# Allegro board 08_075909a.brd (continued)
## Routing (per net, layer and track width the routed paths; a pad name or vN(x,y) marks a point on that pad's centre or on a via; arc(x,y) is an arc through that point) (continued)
THERM: length 154.3
  TOP w0.254: 58.17,112.01 58.79,112.01 59.95,110.85 59.97,110.85 U1.29
  TOP w0.635: J2.13 42.04,115.32 45.47,115.32 48.9,111.89 54.33,111.89 C14.1 55.12,112.01 58.17,112.01
  BOTTOM w0.635: 31.75,165.66 30.78,166.62 23.24,166.62 22.61,165.99 R128.1 22.61,163.6 ; 31.75,165.66 R127.1 ; 31.75,165.66 32.84,166.75 46.99,166.75 48.51,165.23
  BOTTOM w0.762: THERM.1 J5.22 ; J2.13 36.07,121.28
  BOTTOM w0.889: 58.67,165.35 58.67,165.48 57.66,166.5 49.78,166.5 48.51,165.23 R126.1 ; 58.67,165.35 R124.1 ; 58.67,165.35 59.82,166.5 67.82,166.5 68.83,165.48 ; 68.83,165.48 69.98,166.62 77.85,166.62 79.38,165.1 R122.1 ; 68.83,165.48 R123.1 ; 36.07,121.28 THERM.1 ; 22.61,163.6 22.23,163.6 22.17,163.55 22.04,163.55 21.38,162.89 21.38,161.5 21.48,161.4 21.48,161.37 21.85,161 21.87,161 22.17,160.71 24.12,158.75 29.34,158.75 36.07,152.02 J5.21 J5.22
TXLN: length 14.9
  TOP w0.203: R14.1 30.27,142.88 R157.2 27.98,141.59 27.45,141.06 27.45,139.95 D31.C 27.66,139.8 R150.1 TXLN.1
  TOP w0.305: R151.2 25.65,140.21 25.91,139.95 27.45,139.95
TXLN_SDI: length 57.8
  TOP w0.203: 67.61,133.93 67.61,133.65 65.37,131.41 R8.1 R2.2 ; 67.61,133.93 67.87,133.93 69.37,135.43 69.37,137.03 68.99,137.41 70.38,137.41 71.07,138.1 71.07,142.41 69.53,143.94 33.2,143.94 32.26,143 R14.2 ; 67.61,133.93 67.22,134.32 Q1.1
  TOP w0.254: 68.99,137.41 J1.16
TXLNSDI: length 21.3
  TOP w0.203: 69.12,116.97 69.97,116.97 70.76,117.76 70.76,119.29 62.87,127.19 62.87,128.27 63.7,129.11 63.7,130.17 R8.2 ; 69.12,116.97 69.12,116.08 U1.16 ; 69.12,116.97 69.12,116.97 C82.1
TXLP: length 14.7
  TOP w0.203: 27.45,148.59 27.45,147.68 27.98,147.15 R160.2 30.27,145.67 R16.1 ; 27.45,148.59 D28.C 27.66,148.75 R152.1 TXLP.1 ; 27.45,148.59 25.65,148.59 25.4,148.34 R154.2
TXLP_SDO: length 58.7
  TOP w0.203: R16.2 32.13,145.54 33.27,144.4 69.72,144.4 71.53,142.6 71.53,137.91 70.69,137.07 J1.15 70.31,135.71 67.23,132.64 ; 67.23,132.64 65.81,131.22 65.81,130.46 R7.1 67.53,128.74 R4.2 ; 67.23,132.64 67.23,132.51 Q1.4
TXLPSDO: length 21.2
  TOP w0.203: 70.29,115.81 69.55,115.81 68.8,115.05 U1.15 ; 70.29,115.81 C78.1 ; 70.29,115.81 70.21,115.88 70.21,116.63 70.91,117.33 70.91,117.33 71.17,117.58 71.17,119.46 63.27,127.36 63.27,128.09 64.03,128.85 65.02,128.85 R7.2
TXN1: length 14.6
  TOP w0.203: v1(4.17,143.87) 4.32,144.02 6.48,144.02 6.92,143.57 TXLP_CONN.1 7.84,139.48 TXN1.1
  BOTTOM w0.203: R20.1 11.11,138.3 TXN1.1 ; CM2.1 5.73,143.56 5.42,143.87 v1(4.17,143.87)
TXN2: length 8.1
  TOP w0.203: L1.1 104.8,126.81 107.25,126.81 D33.2 107.27,126.81 109.41,126.81 109.73,126.49 R179.2
TXP1: length 14.3
  TOP w0.203: TXP1.1 7.84,148.68 TXLP_CONN.2 6.9,145.07 6.9,145.07 6.35,144.53 4.43,144.53 v1(4.2,144.76)
  BOTTOM w0.203: v1(4.2,144.76) 4.43,144.53 5.42,144.53 5.73,144.83 CM2.2 ; TXP1.1 11.49,149.86 R27.1
TXP2: length 8.3
  TOP w0.203: L2.1 105.06,128.71 107.25,128.71 D33.1 107.27,128.71 109.41,128.71 109.98,129.29 R180.2
TXUN: length 18.8
  TOP w0.203: 97.38,123.7 D30.C 97.38,123.74 97.38,126.42 R158.2 R15.1 ; 97.38,123.7 97.38,122.83 98.2,122.02 R134.1 103.25,121.28 TXUN.1 ; 97.38,123.7 99.92,123.7 100.43,124.21 R133.2
TXUN_SCLK: length 25.1
  TOP w0.203: R15.2 93.64,127.09 93.12,127.61 82.65,127.61 81.47,126.42 J1.9
  BOTTOM w0.203: Q2.1 79.44,122.95 78.87,123.51 ; 78.87,123.51 76.8,121.44 R5.1 R3.2 ; 78.87,123.51 80.3,124.93 J1.9
TXUNSCLK: length 13.2
  TOP w0.203: U1.9 70.94,112.95 v1(71.2,112.95)
  BOTTOM w0.203: R5.2 75.31,118.75 74.39,118.75 69.6,113.95 69.6,113.16 70.1,112.65 70.89,112.65 v1(71.2,112.95) 71.2,112.98 C76.1
TXUP: length 17.5
  TOP w0.203: D26.C 97.34,129.4 R159.2 R13.1 ; D26.C 97.37,132.11 R147.1 TXUP.1 ; D26.C 99.94,132.08 100.45,131.57 R146.2
TXUP_CS0: length 25.6
  TOP w0.203: J1.10 81.2,126.73 82.48,128.02 93.09,128.02 93.64,128.56 R13.2
  BOTTOM w0.203: 77.72,122.94 77.31,123.35 Q2.4 ; 77.72,122.94 76.42,121.63 R6.1 R1.2 ; 77.72,122.94 79.67,124.88 J1.10
TXUPCS0: length 15.7
  TOP w0.203: U1.10 69.03,111.74 69.03,111.08 68.64,110.7 v1(68.58,110.7)
  BOTTOM w0.203: C79.1 68.15,110.19 68.15,110.27 v1(68.58,110.7) 68.58,110.87 69.8,112.09 69.8,112.38 69.19,112.99 69.19,114.12 74.09,119.02 74.09,120.32 R6.2
UARTSEL: length 37.9
  TOP w0.203: J1.4 90.45,118.13 91.95,119.63 UARTSEL.1 91.95,121.54 92.96,120.52 94.87,120.52 97.03,118.36 ; U1.4 71.83,110.22 72.86,111.25 73.41,111.25 v1(76.71,114.55)
  TOP w0.254: R10.2 96.32,115.46 96.32,115.87 97.03,116.59 97.03,117.06 96.57,117.52 R9.1 97.03,117.98 97.03,118.36
  BOTTOM w0.203: J1.4 89.05,114.55 v1(76.71,114.55)
UNNAMED_4_ADES1754XXX_I843_SHDNL: length 6.6
  TOP w0.254: U1.1 72.2,108.55 72.2,108.55 71.88,108.23 v1(71.88,107.98)
  BOTTOM w0.254: v1(71.88,107.98) 72.17,107.98 C2.1 75.35,108.96 R22.1
UNNAMED_4_CAP_I874_N2: length 2.5
  TOP w0.635: C6.2 80.77,98.25 80.77,98.55 R19.1
UNNAMED_7_CAP_I800_N1: length 15.6
  TOP w0.635: ALERTIN_N.1 120.4,113.16 118.7,111.46 118.7,106.7 ALARM_IN_UP.1 116.98,106.36 116.48,106.86 115.01,106.86 C88.1 114.33,106.88 112.78,106.88 111.94,106.05 U5.3
UNNAMED_7_CAP_I800_N2: length 16.8
  TOP w0.635: 111.26,103.5 114.45,103.5 C88.2 114.96,103.45 116.46,103.45 117.87,104.86 ALARM_IN_UP.2 118.7,104.86 118.7,102.92 122.43,99.19 123.7,99.19 ALERTIN_P.1
UNNAMED_7_CAP_I813_N1: length 43.5
  TOP w0.203: v1(30.61,106.3) 24.13,106.3 17.78,99.95 13,99.95 12.95,99.99 ; R136.1 36.45,107.7 v1(34.8,106.05)
  TOP w0.635: R111.2 12.95,98.81 12.22,98.07 C93.1
  L3_GND w0.203: v1(34.8,106.05) 30.86,106.05 v1(30.61,106.3)
UNNAMED_7_CAP_I821_N1: length 7.4
  TOP w0.203: C104.1 18.07,161.72 R186.1 ; R186.1 18.07,165.53 GPIO_AUX5.1 ; R186.1 18.05,163.32 GP/AUX5.1
UNNAMED_7_CAP_I822_N1: length 9.7
  TOP w0.203: GPIO_AUX4.1 38.49,164.78 37.96,164.25 37.96,163.45 R185.1 38.29,163.42 C109.1 40.23,163.41 40.23,162.71 40.51,162.43 GP/AUX4.1
UNNAMED_7_CAP_I841_N1: length 11.5
  TOP w0.203: C17.1 R145.1 88.14,164.82 88.62,164.82 89.66,165.86 91.57,165.86 91.97,165.46 91.97,165.07 ; R137.2 R144.1 94.23,164.82 92.96,164.82 92.94,164.85 R139.1 91.97,164.85 91.97,165.07 ; 92.09,164.8 92.09,164.96 91.97,165.07
UNNAMED_7_CAP_I843_N1: length 4.7
  TOP w0.203: C91.1 113.09,144.27 111.85,145.52 111.42,145.52 110.17,144.27 R162.1
UNNAMED_7_CAP_I844_N1: length 4.7
  TOP w0.203: C92.1 113.09,147.32 111.85,146.08 111.42,146.08 110.17,147.32 R164.1
UNNAMED_7_CAP_I847_N2: length 4
  TOP w0.203: C89.2 13.78,126.12 14.2,126.54 16.56,126.54 17.08,126.02 R172.1
UNNAMED_7_CAP_I848_N2: length 4
  TOP w0.203: R173.1 17.08,128.66 16.81,128.4 14.1,128.4 13.78,128.71 C90.2
UNNAMED_7_CN2P_I834_N2: length 2.4
  BOTTOM w0.254: R122.2 79.32,161.72 THERM1.2
UNNAMED_7_CN2P_I835_N2: length 2.2
  BOTTOM w0.254: THERM2.2 R123.2
UNNAMED_7_CN2P_I836_N2: length 2.3
  BOTTOM w0.254: THERM3.2 R124.2
UNNAMED_7_CN2P_I837_N2: length 2.3
  BOTTOM w0.254: R126.2 48.46,161.72 THERM4.2
UNNAMED_7_CN2P_I838_N2: length 2.7
  BOTTOM w0.203: R127.2 31.75,162.15 32.13,161.77 THERM5.2
UNNAMED_7_CN2P_I839_N2: length 2.7
  BOTTOM w0.203: R128.2 22.61,161.93 23.37,161.16 THERM6.2
UNNAMED_7_CN4P_I840_N2: length 3.7
  TOP w0.381: J8.2 93.73,168.4 94.23,167.89 R144.2
UNNAMED_7_CN4P_I840_N4: length 3.7
  TOP w0.381: R145.2 88.14,167.39 88.65,167.89 J8.4
UNNAMED_7_CN18PODDEVEN2GND_I950_N9: length 160.6
  TOP w0.254: J7.18 69.5,1.62 69.98,1.14 109.47,1.14 117.22,8.89 121.41,8.89 125.73,13.21 125.73,27.43 117.98,35.18 107.7,35.18 102.87,40 R23.1
UNNAMED_7_DIOTVS3PV6_I845_N1: length 10.6
  TOP w0.203: 101.66,146.75 D29.1 101.57,146.85 R161.1 ; 101.66,146.75 102.8,146.75 103.38,147.32 R164.2 ; 101.66,146.75 100.65,146.75 100.08,147.32 R130.1
UNNAMED_7_DIOTVS3PV6_I845_N2: length 10.6
  TOP w0.203: 101.66,144.85 D29.2 101.57,144.74 R155.1 ; 101.66,144.85 103.06,144.85 103.63,144.27 R162.2 ; 101.66,144.85 100.65,144.85 100.08,144.27 R129.1
UNNAMED_7_DIOTVS3PV6_I846_N1: length 10
  TOP w0.203: D32.1 23.52,128.2 22.16,128.2 21.34,129.03 R173.2 20.5,129.45 20.5,131.22 20.85,131.57 R169.1 23.32,131.57 23.69,131.2 R140.1
UNNAMED_7_DIOTVS3PV6_I846_N2: length 9.7
  TOP w0.203: D32.2 22.16,126.3 21.59,125.73 R172.2 20.52,125.29 20.52,123.39 20.73,123.19 R168.1 23.18,123.19 R138.1
UNNAMED_7_DIOTVS_I814_N: length 5.8
  TOP w0.635: ALARM_OUT_LP.2 9.32,105.85 9.32,105.86 9.84,105.86 10.67,106.68 10.67,108.12 ; 10.67,108.12 D10.C ; 10.67,108.12 R112.1
UNNAMED_7_DIOTVS_I815_N: length 5.9
  TOP w0.635: 10.41,102.19 10.41,103.88 9.94,104.35 ALARM_OUT_LP.1 ; 10.41,102.19 R111.1 ; 10.41,102.19 D9.C
UNNAMED_7_ICAT24C0XC_I842_A2: length 7.2
  TOP w0.254: R125.2 50.7,138.05 49.78,138.05 49.33,138.5 48.31,138.5 46.75,136.94 46.31,136.94 45.51,137.74
UNNAMED_7_ICAT24C0XC_I842_SCL: length 8.4
  TOP w0.254: R115.2 48.39,130.18 49.31,130.18 51.13,132 R143.2 51.09,132.16 49.1,134.15
UNNAMED_7_ICAT24C0XC_I842_SDA: length 11.5
  TOP w0.203: R131.2 54.79,133.94 54.42,133.57 R148.1 52.61,133.49 52.1,132.97 51.18,132.97 48.65,135.5 48.36,135.5 47.32,134.47 47.32,134.14 48.2,133.26
UNNAMED_7_ICAT24C0XC_I842_VCC: length 21.6
  TOP w0.508: 53.19,138.15 53.19,138.13 R125.1 52.26,137.4 50.89,136.04 50.89,135.95 49.56,137.29 48.51,137.29 45.52,134.3 45.52,133.04 R115.1 ; 53.19,138.15 54.48,139.45 57.4,139.45 R26.1 ; 53.19,138.15 52.49,137.46 52.49,136.74 R131.1
UNNAMED_7_RES_I895_N1: length 6
  TOP w0.203: R96.1 85.32,25.88 86.61,27.18 86.61,29.74 SW1.7
UNNAMED_7_RES_I895_N2: length 5.8
  TOP w0.203: SW1.6 84.07,29.74 R96.2 84.07,27.46 83.59,27.46 82.02,25.88 R97.1
UNNAMED_7_RES_I896_N2: length 5.8
  TOP w0.203: R98.1 79.48,25.88 81.05,27.46 81.53,27.46 R97.2 81.53,29.74 SW1.5
UNNAMED_7_RES_I897_N2: length 5.8
  TOP w0.203: R99.1 76.94,25.88 78.51,27.46 78.99,27.46 R98.2 78.99,29.74 SW1.4
UNNAMED_7_RES_I898_N2: length 5.8
  TOP w0.203: R100.1 74.4,25.88 75.97,27.46 76.45,27.46 R99.2 76.45,29.74 SW1.3
UNNAMED_7_RES_I899_N2: length 5.8
  TOP w0.203: R101.1 71.86,25.88 73.41,27.43 73.89,27.43 73.91,27.46 R100.2 73.91,29.74 SW1.2
UNNAMED_7_RES_I901_N1: length 8.3
  TOP w0.203: R102.1 67.79,25.88 69.37,27.46 71.37,27.46 R101.2 71.37,29.74 SW1.1
UNNAMED_7_RES_I901_N2: length 5.7
  TOP w0.203: SW2.8 R102.2 66.29,27.46 65.81,27.46 64.24,25.88 R103.1
UNNAMED_7_RES_I902_N2: length 5.7
  TOP w0.203: SW2.7 R103.2 63.75,27.46 63.27,27.46 61.7,25.88 R104.1
UNNAMED_7_RES_I903_N2: length 5.7
  TOP w0.203: SW2.6 R104.2 61.21,27.46 60.73,27.46 59.16,25.88 R105.1
UNNAMED_7_RES_I905_N1: length 5.7
  TOP w0.203: SW2.5 R105.2 58.67,27.46 58.19,27.46 56.62,25.88 R106.1
UNNAMED_7_RES_I905_N2: length 5.7
  TOP w0.203: SW2.4 R106.2 56.13,27.46 55.65,27.46 54.08,25.88 R107.1
UNNAMED_7_RES_I907_N1: length 5.7
  TOP w0.203: R108.1 51.54,25.88 53.09,27.43 53.57,27.43 53.59,27.46 R107.2 SW2.3
UNNAMED_7_RES_I907_N2: length 5.7
  TOP w0.203: R109.1 49,25.88 50.55,27.43 51.03,27.43 51.05,27.46 R108.2 SW2.2
UNNAMED_7_RES_I908_N2: length 2.4
  TOP w0.203: R109.2 SW2.1
UNNAMED_7_RES_I921_N1: length 2.6
  TOP w0.635: R113.1 99.47,104.78 U5.5
UNNAMED_8_ADMAX3390E_I407_3STATEN: length 17
  TOP w0.203: U4.8 121.84,75.65
  TOP w0.381: R132.2 122.91,60.86 121.84,61.93 U2.8 121.84,64.05 122.68,64.9 122.68,72.77 121.84,73.62 121.84,75.65
UNNAMED_8_ADMAX3390E_I407_IVCC1: length 62.1
  TOP w0.203: U4.13 118.59,76.93 v1(119.06,77.41)
  BOTTOM w0.203: v1(119.06,77.41) 109.51,77.41 91.16,95.76 88.52,95.76 86.97,97.31 79.22,97.31 73.66,102.87 73.66,104.01 R141.2
UNNAMED_8_ADMAX3390E_I407_OVL1: length 69.3
  TOP w0.381: v1(118.62,67.82) 118.59,67.84 118.59,69.85 U4.2 118.59,71.19 118.28,71.5 116.97,71.5 116.2,70.74 114.3,70.74 111.91,73.13 111.91,96.24 110.62,97.54 R142.2 110.62,98.4 ; v1(117.86,54.61) 116.84,53.59 110.11,53.59 109.35,52.83 109.35,48.26 MINIQ1.4
  BOTTOM w0.254: D24.1 MINIQ1.4
  BOTTOM w0.381: v1(118.62,67.82) 117.35,66.55 117.35,55.12 v1(117.86,54.61)
UNNAMED_8_CAP_I399_N1: length 11.4
  TOP w0.203: v1(8.89,142.62) 9.54,142.62 9.79,142.88 R181.1
  TOP w0.635: C101.1 12.06,138.75 12.06,140.17 10.86,141.36 R181.1
  BOTTOM w0.203: 10.26,143.02 9.29,143.02 v1(8.89,142.62) ; 10.26,143.02 10.28,143.02 10.28,141.77 11.39,140.65 R20.2 ; 10.26,143.02 CM2.4
UNNAMED_8_CAP_I400_N2: length 11.6
  TOP w0.203: R182.1 9.78,145.67 9.4,146.05 v1(8.89,146.05)
  TOP w0.635: R182.1 10.86,147.51 12.06,148.71 12.06,149.91 C102.2
  BOTTOM w0.203: v1(8.89,146.05) 9.42,145.52 CM2.3 10.28,145.53 10.28,146.78 11.39,147.89 R27.2
UNNAMED_8_CN2P2GND_I383_N1: length 10.2
  TOP w0.203: TXUP_CONN.1 120.6,128.64 120.84,128.4 v1(120.9,128.4)
  BOTTOM w0.203: CM1.1 121.57,128.67 121.57,128.67 121.29,128.4 v1(120.9,128.4) 119.95,129.35 R184.1 119.95,132.73 TXP2.1
UNNAMED_8_CN2P2GND_I383_N2: length 10
  TOP w0.203: TXUP_CONN.2 120.6,127.14 120.9,127.44 v1(120.9,127.51)
  BOTTOM w0.203: TXN2.1 120.08,123.12 R183.1 120.08,126.68 v1(120.9,127.51) 121.42,127.51 121.62,127.31 121.62,127.31 CM1.2
UNNAMED_8_CN8PA_I435_N7: length 2
  BOTTOM w0.381: MINIQ2.7 120.83,96.86 R24.1
UNNAMED_8_DIOTVS2PV4_I413_N1: length 55.7
  TOP w0.203: v1(105.66,50.04) MINIQ1.2
  TOP w0.254: v1(105.66,50.04) 105.66,73.02 106.88,74.24 106.88,95.96 107.95,97.03 R114.2
  BOTTOM w0.254: D25.1 103.89,46.1 104.9,47.12 MINIQ1.2
UNNAMED_8_DIOTVS2PV4_I415_N1: length 2.6
  BOTTOM w0.203: D23.1 MINIQ1.6
UNNAMED_8_DIOTVS2PV4_I416_N1: length 2.6
  BOTTOM w0.203: D22.1 MINIQ1.8
UNNAMED_8_DIOTVS2PV4_I417_N1: length 2.6
  BOTTOM w0.203: D21.1 MINIQ1.10
UNNAMED_8_DIOTVS3PV6_I401_N1: length 8.3
  TOP w0.203: R182.2 16.05,145.67 16.49,145.23 D34.1 18.69,145.23 19.25,145.8 L4.1
UNNAMED_8_DIOTVS3PV6_I401_N2: length 8.3
  TOP w0.203: L3.1 19.25,142.75 18.68,143.32 16.84,143.32 D34.2 16.52,143.31 16.08,142.88 R181.2
UNNAMED_8_FERRITE_I392_N2: length 4.4
  TOP w0.203: L1.2 102.63,126.49 101.49,127.64 100.8,127.64 99.65,126.49 R158.1
UNNAMED_8_FERRITE_I393_N2: length 4.4
  TOP w0.203: R159.1 99.65,129.29 100.8,128.14 101.49,128.14 102.63,129.29 L2.2
UNNAMED_8_FERRITE_I402_N2: length 2.7
  TOP w0.203: L3.2 25.35,142.75 25.47,142.88 R157.1
UNNAMED_8_FERRITE_I403_N2: length 2.7
  TOP w0.203: L4.2 25.35,145.8 25.47,145.67 R160.1
UNNAMED_8_FLTR4PV7_I388_N3: length 6.2
  TOP w0.203: R179.1 115.33,125.97 v1(116.2,125.09)
  BOTTOM w0.203: v1(116.2,125.09) 116.59,124.71 R183.2 118.18,126.21 CM1.3
UNNAMED_8_FLTR4PV7_I388_N4: length 6.1
  TOP w0.203: v1(116.46,130.68) 115.33,129.56 R180.1
  BOTTOM w0.203: 117.88,131.32 117.88,131.01 117.35,130.48 117.35,129.53 CM1.4 ; 117.88,131.32 117.09,131.32 v1(116.46,130.68) ; 117.88,131.32 R184.2
VAA: length 58.8
  TOP w0.254: U1.3 72.1,109.87 72.85,110.62 72.89,110.58 74,110.58
  TOP w0.381: J1.3 93.1,113.3 ; J1.3 93.1,115.01 ; J1.3 91.39,113.3 ; R11.1 79.78,112.75 ; R11.1 81.07,113.7 ; R11.1 78.7,113.7
  TOP w0.508: 74,110.58 C3.1 C15.1 75.91,109.92 76.61,109.22
  TOP w0.635: v1(113.13,99.06) R32.1 ; VAA.1 94.49,117.29 R9.2
  L3_GND w0.635: v1(113.13,99.06) 112.29,99.9 112.29,113.61 106.83,119.08 VAA.1
  L3_GND w0.762: J1.3 92.24,118.09 93.28,119.13 94.49,119.13 VAA.1
VBLKP: length 40.5
  TOP w0.254: R18.2 88.14,93.4 88.14,92.46 93.47,87.12 VBLK.1 ; U1.60 71.38,105.08 70.74,105.72 70.08,105.72 v1(69.99,105.81)
  TOP w0.305: J4.12 C21.1 90.63,95.46 89.79,94.61 89.46,94.61 88.92,94.07 R18.2
  L3_GND w0.254: J4.12 85.79,100.33 80.84,100.33 80.51,100.66 80.02,100.66 79.69,100.33 75.69,100.33 73.53,102.49 73.53,103.12 70.85,105.81 v1(69.99,105.81)

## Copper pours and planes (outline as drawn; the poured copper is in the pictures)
GND_POWER on TOP: 78.23,103.12 80.77,100.58 80.77,100.08 80.26,99.57 79.76,99.57 77.22,102.11
GND_POWER on L2_GND: 0.51,173.74 126.49,173.74 126.49,0.51 0.51,0.51
GND_POWER on L3_GND: 0.51,173.74 126.49,173.74 126.49,0.51 0.51,0.51 ; 11 cut-outs
VDDL2/VDDL3 on L3_GND: 58.34,133.25 60.45,131.14 60.45,117.09 64.01,113.54 64.01,111.51 66.55,108.97 70.61,108.97 74.3,105.28 74.3,105.03 95,105.03 95.5,105.54 96.39,105.54 99.11,102.82 103.58,102.82 104.65,103.89 104.65,104.14 101.98,106.81 85.85,106.81 62.36,130.3 62.36,130.94 62.74,131.32 62.74,131.19 66.55,127.38 69.85,127.38 75.74,121.49 79.27,121.49 80.42,120.6 81.03,121.36 78.33,123.75 77.5,124.56 77.5,125.45 82.3,130.26 80.77,132.08 78.78,131.74 78.79,131.75 69.09,131.75 67.06,133.78 67.06,137.34 65.71,137.34 65.71,133.86 63.74,133.86 62.69,134.87 58.34,134.87
(no net) on BOTTOM: 0.51,173.74 126.49,173.74 126.49,0.51 0.51,0.51 ; 89 cut-outs
DCIN on TOP: 74.68,99.57 74.68,97.54 77.47,94.74 78.74,94.74 79.76,95.76 77.72,97.79 78.36,98.42 75.95,100.84 75.44,100.84 73.53,102.74 73.53,103.84 72.62,104.75 72.62,101.63
HV on TOP: 72.9,107.19 94.87,107.19 97.03,105.03 97.03,104.14 96.39,103.5 95.5,103.5 94.74,104.27 86.61,104.27 84.71,102.36 84.71,101.73 83.5,100.52 82.67,101.35 81.97,100.65 76.96,105.66 73.41,105.66 72.39,106.68
VAA on TOP: 91.87,115.75 92.79,115.75 94.49,114.05 89.03,108.58 74.3,108.58 72.67,110.21 72.67,110.59 73.41,111.33 73.46,111.33 74.56,110.23 75.94,111.61 75.94,111.65 76.19,111.4 76.19,111.12 74.93,109.86 75.83,108.96 77.18,110.32 77.18,110.88 75.07,112.99 76.63,114.55 79.14,114.55 79.14,113.03 80.42,113.03 80.42,114.55 90.68,114.55

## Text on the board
Ref Des/Silkscreen Bottom: CM2
User.Comments: SEE NOTE 7 | SEE NOTE 9 | 7.    INSTALL JUMPER SHUNT (M031256) ON LOCATIONS BELOW: | 9.    ATTACH STICKER LABEL PER U1 COMPONENT BOM VARIANT DECLARATION: | 5.    INSTALL SCREW (M025339) ON PRIMARY SIDE AND STANDOFFS (M025474) ON SECONDARY SIDE. | 6.    DEFAULT SETTINGS TO BE IN ( ON ) POSITION. | 4.    SMOOTHEN EDGES AND FREE FROM BURRS AFTER DEPANELIZATION PROCESS. | * ADES1752EVKIT# FOR 05-075909-04 | * ADES1755EVKIT# FOR 05-075909-02 | * ADES1756EVKIT# FOR 05-075909-03 | * ADES1754EVKIT# FOR 05-075909-01 | B. P+B14 | A. BOP- | SEE NOTE 6 (2 PLACES) | SEE NOTE 5 (4 PLACES)
Ref Des/Assembly Top: C | A | ON | SPI KIT | UART KIT
Ref Des/Silkscreen Top: C | A | MINIQ1 | TXN2 | SPI KIT | UART KIT
DIMENSION: " " | (REF) | DIAMAX
PAGE_OUTLINE: 05JUN23 | ADES175X_EVKIT_A
User.15: L2_GND | 08-      -07
User.16: L3_GND | 08-      -08
User.25: NOTE: DO NOT EDIT THIS TABLE MANUALLY:USE IMPEDANCE TABLE GENERATOR FROM MAXIMTOOLS. | FAB NOTES REVISION: 2ND NOVEMBER 2022 | (THICKNESS AFTER PLATING) | 1 OZ, 0.0014" | 0.006 | 0.045 | FINAL CU | CU CLAD | 8.   IMPEDANCE REQUIREMENTS: IF NO STACKUP IS DEFINED, THE VENDOR IS ALLOWED TO ADJUST THE DIELECTRIC | 13.  PLATING SPECIFICATION: | 1.   DIMENSIONS ARE IN INCHES (EXCEPT WHERE NOTED). | ALL DOCUMENTS & SPECIFICATIONS REFERRED TO BELOW SHOULD BE THE LATEST REVISIONS. | 2.  BOARD MATERIAL:(USE CHECKED ITEMS) | 3.   ALL LAMINATES & BONDING MATERIALS SHOULD BE SELECTED FROM IPC-4101 OR IPC-4103,(TG>170 DEGC TD>300 DEGC) | 4.   REFER TO IPC-6010 SERIES, CLASS 2 FOR FABRICATION. | 5.   REFER TO LAMINATION DIAGRAM FOR OVERALL BOARD THICKNESS, TOLERANCE APPLIES AFTER ALL LAMINATION AND PLATING | 6.   BOW & TWIST NOT TO EXCEED 0.0075 INCHES (0.75%) PER LINEAR INCH AND SHOULD BE MEASURED PER IPC-TM-650, METHOD 2.4.22. | 7.   ACCEPTABILITY PER ADI SPECIFICATION TST00115. | 9.   FILLET OPTIONS TO ENHANCE RELIABILITY AT PAD JUNCTIONS WHERE SPACING PERMITS. | 10.  THIEVING: | 11.  LAYER TO LAYER REGISTRATION SHALL BE WITHIN 0.003 INCHES. | 12.  DRILL SIZES ARE FINISHED HOLE SIZES. ALL HOLES SHALL BE LOCATED WITHIN 0.005 INCHES DTP,UNLESS SPECIFIED. | 14.  SURFACE FINISH: | 15.  SOLDERMASK: | 16.  APPLY SILKSCREEN TO BOTH SIDES USING A NON-CONDUCTIVE, EPOXY BASED INK PER ARTWORK. | (X) WHITE | ( ) OTHER | PROCESSES. FINISHED THICKNESS MEASURED FROM TOP COPPER TO BOTTOM COPPER. | (X)  ISOLA 370HR OR S1000-2 OR IT180 OR EQUIVALENT | ( )  ISOLA-FR408HR OR EQUIVALENT | ( )  ISOLA IS410 | ( )  MEGTRON 6 | ( )  NELCO-4000-13 | ( )  ROGERS 4350B | ( ) ROGERS 3003 | ( ) ARLON 85N | ( ) EM370D | ( )  OTHER ________________________ | ( ) FILLETS ALLOWED | (X) FILLETS NOT ALLOWED | ( ) VENDOR MAY ADD THIEVING TO COMPENSATE FOR LOW COPPER DENSITY AREAS MAINTAINING A MINIMUM | (X) VENDOR MAY NOT ADD THIEVING TO COMPENSATE FOR LOW COPPER DENSITY AREAS. | (X) LPI | ( ) OTHER_________ | COLOR | (X) GREEN | HINDER PROPER SOLDER WICKING. BARREL RELIEF ON SOLDERMASK ALLOWED IN UNFILLED VIA IN PAD HOLES. | (X) REFER TO LAMINATION DIAGRAM FOR FINISHED COPPER WEIGHT/THICKNESS REQUIRMENTS | (X) IMMERSION GOLD (ENIG) 1.58-3.94 MICRO INCHES OVER 118-236 MICRO INCHES MIN. OF ELECTROLESS NICKEL PER IPC-4552 | ( ) OSP (ORGANIC SOLDERABILITY PRESERVATIVE) | ( ) IMMERSION SILVER | ( ) SOFT WIRE BONDABLE GOLD 30-50 MICRO INCHES OF SOFT WIRE | ( ) EDGE CONNECTOR FINGERS ARE TO BE PLATED WITH 100 MICRO-INCHES(.0001") OF LOW STRESS | THICKNESS & TRACE WIDTHS TO MEET THE IMPEDANCE REQUIREMENT. IF SPECIFIED, THE VENDOR MUST | TRACE WIDTH & SPACING THAT IMPACT THE REQUIREMENTS MUST HAVE WRITTEN APPROVAL FROM ADI. | MINIMUM BARREL PLATING OF 0.001 INCHES. PLATED HOLES SHALL NOT BE ROUGH OR IRREGULAR SO AS TO | SOLDERMASK OVER BARE COPPER OR BARE GOLD (BOTH SIDES) TO MEET IPC-SM-840. | IF PRESENT,DO NOT MODIFY SOLDERMASK DEFINED PADS (MASK OPENINGS LESS THAN COPPER PAD) WITHOUT APPROVAL. | MEET THE REQUIREMENTS LISTED IN THE IMPEDANCE TABLE. ANY ADJUSTMENT MADE TO THE DEFINED STACKUP, | UL FLAMMABILITY RATING 94V-0. BOARD MATERIAL & CONSTRUCTION SHALL MEET THE REQUIREMENTS OF UL796/UL796F. | BONDABLE GOLD OVER 100-150 MICRO INCHES OF NICKEL | NICKEL UNDER 30 MICRO-INCHES (.0003') OF GOLD | 0.100 INCH CLEARANCE FROM ALL COPPER FEATURES, | THE STARTING COPPER WEIGHT/THICKNESS CAN VARY AS LONG AS THE FINISHED COPPER | WEIGHT/THICKNESS IS NOT LESS THAN THE SPECIFIED VALUE. | UNLESS OTHERWISE SPECIFIED | HOMOGENOUS MATERIALS IN THIS BOARD SHALL BE COMPLAINT WITH THE EU DIRECTIVE 2002/95/EC | WORKMANSHIP SHALL CONFORM TO IPC-A-600, CLASS 2. | IMPEDANCE TOLERANCE: +/-10% | LAYER | BOTTOM | TOP | GND3 | TRACE WIDTH | 0.01000 | 0.00700 | 50 OHM | 21.  INTENTIONAL SHORTS: | 17.  FINAL ELECTRICAL TEST TO BE PERFORMED USING PROVIDED IPC-D-356A NETLIST OR ODB++ FORMAT FILE. | 22.  PEMNUTS: | 23.  MANUFACTURER TO ETCH/STAMP WITH PERMANENT NON-CONDUCTIVE INK | ON SECONDARY SIDE UNLESS OTHERWISE SPECIFIED: | 18.  A TIME DOMAIN REFLECTOMETER REPORT (TDR) FOR EACH IMPEDANCE CONTROLLED LAYER & A CERTIFICATE | 19.  IF PRESENT, ALL BLIND/BURIED VIAS WITH AN ASPECT RATIO <1:1 TO BE PLATED SHUT WITH COPPER WHEN | 20.  FOR VIA FILL INFORMATION REFER TO DRILL CHART: | 25. PANELIZATION: | 27.  MINIMUM DESIGN LINE WIDTH IS .005 INCH. | 28.  MINIMUM DESIGN LINE SPACING IS .008 INCH. | IMPEDANCE TABLE | - | 65 OHM | IS ACCEPTABLE, ALL OTHER INSTANCES MUST BE REPORTED. | IF AN INTENTIONAL SHORT REPORT IS SUPPLIED AND DOES NOT MATCH THE FAB DATA THEN | THE PCB SHALL HAVE A VERIFICATION STAMP. | ( )  NON-CONDUCTIVE EPOXY FILL ALL 0.XXXX INCHES DRILLED VIAS | ( )  COPPER FILL ALL 0.XXXX INCHES DRILLED VIAS | ( ) PEMNUTS TO BE INSTALLED BY FABRICATOR | ( ) PEMNUTS NOT TO BE INSTALLED BY FABRICATOR | (X) NOT APPLICABLE | USED AS VIA-IN-PAD OR AS A STACKED VIA. BLIND/BURIED VIAS WITH AN ASPECT RATIO >1:1 TO BE FILLED | A. UL CODE-FLAMMABILITY RATING FOR THOSE APPROVED MATERIALS(IF APPLICABLE) | B. DATE CODE | C. LOT NUMBER | D. MANUFACTURER LOGO | BOARDS TO BE SHIPPED IN ARRAY AND KEPT INTACT | PANEL TO BE SUBJECTED TO CUSTOMERS APPROVAL | PANEL SOLDER PASTE STENCIL GERBER TO BE PROVIDED TO ANALOG | CAN'T BE PERFORMED BECAUSE THE TRACE LENGTH IS TOO SHORT ON THE OUTER LAYERS AT THE PIN ESCAPES | ADI APPROVAL IS REQUIRED. | OF COMPLIANCE SHALL BE PROVIDED BY VENDOR AT TIME OF SHIPMENT. INSTANCES WHERE TDR TESTING | WITH NON-CONDUCTIVE EPOXY. | NUMBER | THE FINISHED PCB THICKNESS TO BE: | 1 | 2 | 3 | 4 | L2_GND | L3_GND | TRACE WIDTH/SPACE | 0.00800/0.00800 | NAME | 100 OHM | COPPER THICKNESS | (OZ,INCH) | LAMINATION DIAGRAM | 4 LAYER STACKUP | 75 OHM | 0.062" +/-10% | DIELECTRIC | THICKNESS (INCH) | ISOLA 370HR/EQUIVALENT | MATERIALS | NOTES: | TOOLING: | FINISH: | MATERIAL: | TESTING: | MISCELLANEOUS:
User.45: FIGURE | SIZE | 10.0 | 30.0 | 39.37 | 40.0 | 45.0 | 187.01 | DRILL CHART: TOP to BOTTOM | FINISHED HOLES IN MILS | PLATED | NON-PLATED | QTY | 507 | 3 | 42 | 103 | 158 | 4 | TOLERANCE/NOTES
